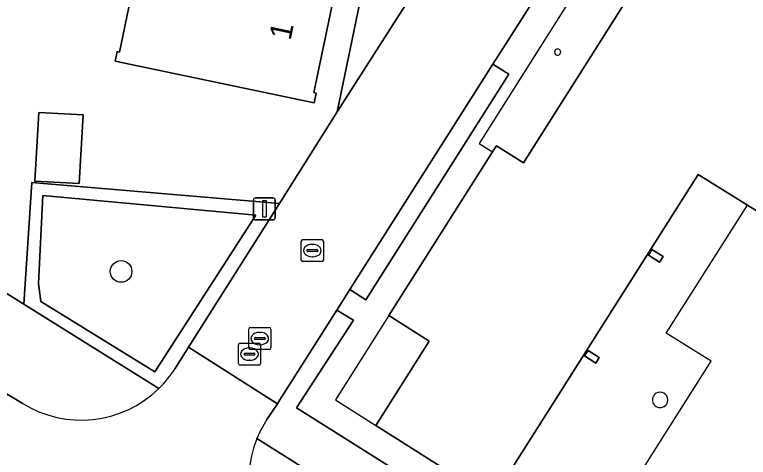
# Model space of a CAD drawing. Extents: x 160102 to 160934, y 382045 to 382923.
# Drawn here: x 160600.16 to 160633.3, y 382504.65 to 382524.66 of the extents above; entities that cross this region are included whole.
import ezdxf

# ---------------------------------------------------------------- set-up
doc = ezdxf.new("R2010")
doc.units = 0
for name, color, linetype in [('IMGEO_Boom', 7, 'Continuous'), ('IMGEO_Erf', 7, 'Continuous'), ('IMGEO_Groenvoorziening', 7, 'Continuous'), ('IMGEO_Haag', 7, 'Continuous'), ('IMGEO_Kolk', 7, 'Continuous'), ('IMGEO_Lichtmast', 7, 'Continuous'), ('IMGEO_Pand', 7, 'Continuous'), ('IMGEO_Pand_nummerreeks', 7, 'Continuous'), ('IMGEO_Pand_overbouw', 7, 'Continuous'), ('IMGEO_Rijbaan_lokaal_open', 7, 'Continuous'), ('IMGEO_Rioolput', 7, 'Continuous'), ('IMGEO_Voetpad_open', 7, 'Continuous')]:
    doc.layers.add(name, color=color, linetype=linetype)

msp = doc.modelspace()

# ---------------------------------------------------------------- linework, layer by layer
at = {"layer": 'IMGEO_Boom'}
msp.add_circle((160604.963, 382513.056), 0.489, dxfattribs=at)
at = {"layer": 'IMGEO_Erf'}
for points in [[(160597.213, 382513.675), (160600.569, 382511.579), (160600.937, 382517.084), (160612.115, 382516.132), (160614.729, 382520.276), (160621.393, 382552.466), (160644.153, 382585.048), (160643.411, 382585.751)], [(160661.29, 382563.07), (160652.176, 382568.858), (160644.821, 382557.292), (160644.14, 382557.763), (160641.367, 382553.385), (160642.088, 382552.972), (160635.737, 382542.872), (160634.993, 382543.323), (160634.373, 382542.344), (160635.122, 382541.901), (160631.677, 382536.462), (160630.951, 382536.942), (160630.329, 382535.96), (160631.075, 382535.503), (160624.503, 382525.174), (160623.784, 382525.627), (160621.753, 382522.421), (160622.486, 382521.975), (160616.017, 382511.774), (160615.304, 382512.24), (160614.712, 382511.306), (160615.463, 382510.851), (160612.895, 382506.892), (160621.64, 382501.381)], [(160623.035, 382501.942), (160616.467, 382506.097), (160618.877, 382509.909), (160617.058, 382511.061), (160621.744, 382518.47), (160621.915, 382518.741), (160623.138, 382517.968), (160628.549, 382526.524), (160627.327, 382527.296), (160632.166, 382534.971), (160633.99, 382533.819), (160638.509, 382540.958), (160636.686, 382542.112), (160641.372, 382549.513), (160641.543, 382549.784), (160642.75, 382549.033), (160649.656, 382559.892), (160648.437, 382560.667), (160652.564, 382567.156), (160660.609, 382562.063)], [(160656.657, 382547.701), (160653.009, 382541.939), (160650.588, 382543.471), (160648.386, 382544.865), (160634.7, 382523.243), (160636.962, 382521.806), (160639.295, 382520.324), (160635.687, 382514.541), (160633.257, 382516.056), (160631.03, 382517.445), (160622.018, 382503.2)], [(160614.735, 382526.271), (160613.666, 382521.142), (160613.774, 382521.12), (160613.683, 382520.684), (160604.691, 382522.561), (160604.781, 382522.997), (160604.889, 382522.975), (160605.736, 382527.058)]]:
    msp.add_lwpolyline(points, dxfattribs=at)
for points in [[(160603.248, 382520.134), (160603.071, 382517.029), (160601.074, 382517.143), (160601.251, 382520.248)], [(160629.447, 382513.727), (160629.287, 382513.473), (160628.78, 382513.794), (160628.94, 382514.048)], [(160626.564, 382509.169), (160626.403, 382508.916), (160625.896, 382509.237), (160626.057, 382509.49)]]:
    msp.add_lwpolyline(points, close=True, dxfattribs=at)
for centre, radius, start, end in [((160624.682, 382522.973), 0.14, 119.8953, 359.7956), ((160624.682, 382522.974), 0.14, 359.6914, 119.9995), ((160629.312, 382507.253), 0.35, 0.0178, 120), ((160629.312, 382507.253), 0.35, 120.0178, 0)]:
    msp.add_arc(centre, radius, start, end, dxfattribs=at)
at = {"layer": 'IMGEO_Groenvoorziening'}
for points in [[(160621.753, 382522.421), (160615.304, 382512.24), (160616.017, 382511.774), (160622.486, 382521.975)], [(160611.05, 382515.602), (160606.488, 382508.518), (160601.346, 382511.706), (160601.235, 382512.516), (160601.432, 382516.495)], [(160611.05, 382515.602), (160601.432, 382516.495), (160601.235, 382512.516), (160601.346, 382511.706), (160606.488, 382508.518)]]:
    msp.add_lwpolyline(points, close=True, dxfattribs=at)
for points in [[(160600.937, 382517.084), (160600.569, 382511.579), (160606.673, 382507.766)], [(160607.407, 382508.669), (160608.012, 382509.628), (160612.115, 382516.132), (160600.937, 382517.084)], [(160612.895, 382506.892), (160615.463, 382510.851), (160614.712, 382511.306), (160612.141, 382507.247), (160612.026, 382507.073), (160611.554, 382506.362)], [(160611.1, 382505.501), (160620.525, 382499.569), (160621.64, 382501.381), (160612.895, 382506.892)]]:
    msp.add_lwpolyline(points, dxfattribs=at)
for centre, radius, start, end in [((160603.16, 382511.372), 5.034, 314.2573, 327.5311), ((160615.692, 382503.63), 4.959, 146.5654, 157.8298)]:
    msp.add_arc(centre, radius, start, end, dxfattribs=at)
at = {"layer": 'IMGEO_Haag'}
for points in [[(160612.115, 382516.132), (160600.937, 382517.084), (160600.569, 382511.579), (160606.673, 382507.766)], [(160607.407, 382508.669), (160608.012, 382509.628), (160612.115, 382516.132)]]:
    msp.add_lwpolyline(points, dxfattribs=at)
msp.add_lwpolyline([(160606.488, 382508.518), (160601.346, 382511.706), (160601.235, 382512.516), (160601.432, 382516.495), (160611.05, 382515.602)], close=True, dxfattribs=at)
msp.add_arc((160603.16, 382511.372), 5.034, 314.2573, 327.5311, dxfattribs=at)
at = {"layer": 'IMGEO_Kolk'}
for p, q in [((160613.103, 382513.574), (160613.103, 382514.426)), ((160613.178, 382514.5), (160614.03, 382514.5)), ((160613.591, 382514.28), (160613.616, 382514.28)), ((160614.104, 382514.426), (160614.104, 382513.574)), ((160613.362, 382513.994), (160613.362, 382514.006)), ((160613.8, 382513.957), (160613.402, 382513.957)), ((160613.405, 382514.043), (160613.803, 382514.043)), ((160613.846, 382514.006), (160613.846, 382513.994)), ((160613.614, 382513.72), (160613.589, 382513.72)), ((160614.03, 382513.5), (160613.178, 382513.5))]:
    msp.add_line(p, q, dxfattribs=at)
for points in [[(160613.103, 382513.574), (160613.103, 382514.426)], [(160613.178, 382514.5), (160614.03, 382514.5)], [(160614.104, 382514.426), (160614.104, 382513.574)], [(160614.03, 382513.5), (160613.178, 382513.5)]]:
    msp.add_lwpolyline(points, dxfattribs=at)
for centre, radius, start, end in [((160613.18, 382514.424), 0.0765, 91.552, 178.448), ((160613.18, 382514.424), 0.0765, 91.552, 178.448), ((160614.028, 382514.424), 0.0765, 1.552, 88.448), ((160614.028, 382514.424), 0.0765, 1.552, 88.448), ((160613.402, 382514.003), 0.0403, 85.8775, 175.7526), ((160613.399, 382513.993), 0.0366, 178.938, 274.7102), ((160613.803, 382514), 0.043, 264.8664, 352.4533), ((160613.807, 382514.005), 0.0386, 1.7309, 96.639), ((160613.18, 382513.576), 0.0765, 181.552, 268.448), ((160613.18, 382513.576), 0.0765, 181.552, 268.448), ((160614.028, 382513.576), 0.0765, 271.552, 358.448), ((160614.028, 382513.576), 0.0765, 271.552, 358.448)]:
    msp.add_arc(centre, radius, start, end, dxfattribs=at)
for centre, major_axis, ratio, start_param, end_param in [((160613.59, 382514), (-0.387, 0.002), 0.722429, 4.712389, 7.853982), ((160613.615, 382514), (-0.39, 0.002), 0.717154, 1.570796, 4.712389)]:
    msp.add_ellipse(centre, major_axis=major_axis, ratio=ratio, start_param=start_param, end_param=end_param, dxfattribs=at)
at = {"layer": 'IMGEO_Lichtmast'}
for p, q in [((160610.94, 382515.484), (160610.94, 382516.284)), ((160610.94, 382516.284), (160610.94, 382515.484)), ((160611.04, 382516.384), (160611.83, 382516.384)), ((160611.83, 382516.384), (160611.04, 382516.384)), ((160611.93, 382516.284), (160611.93, 382515.484)), ((160611.93, 382515.484), (160611.93, 382516.284)), ((160611.83, 382515.384), (160611.04, 382515.384)), ((160611.04, 382515.384), (160611.83, 382515.384))]:
    msp.add_line(p, q, dxfattribs=at)
msp.add_lwpolyline([(160611.36, 382516.259), (160611.51, 382516.259), (160611.51, 382515.509), (160611.36, 382515.509), (160611.36, 382516.259)], dxfattribs=at)
for centre, start, end in [((160611.04, 382516.284), 90, 180), ((160611.04, 382516.284), 90, 180), ((160611.83, 382516.284), 0, 90), ((160611.83, 382516.284), 360, 90), ((160611.04, 382515.484), 180, 270), ((160611.04, 382515.484), 180, 270), ((160611.83, 382515.484), 270, 0), ((160611.83, 382515.484), 270, 0)]:
    msp.add_arc(centre, 0.1, start, end, dxfattribs=at)
at = {"layer": 'IMGEO_Pand'}
for points in [[(160660.609, 382562.063), (160652.564, 382567.156), (160648.437, 382560.667), (160649.656, 382559.892), (160642.75, 382549.033), (160641.543, 382549.784), (160641.372, 382549.513), (160636.686, 382542.112), (160638.509, 382540.958), (160633.99, 382533.819), (160632.166, 382534.971), (160627.327, 382527.296), (160628.549, 382526.524), (160623.138, 382517.968), (160621.915, 382518.741), (160621.744, 382518.47), (160617.058, 382511.061), (160618.877, 382509.909), (160616.467, 382506.097), (160623.035, 382501.942)], [(160622.018, 382503.2), (160631.03, 382517.445), (160633.257, 382516.056), (160635.687, 382514.541), (160639.295, 382520.324), (160636.962, 382521.806), (160634.7, 382523.243), (160648.386, 382544.865), (160650.588, 382543.471), (160653.009, 382541.939), (160656.657, 382547.701)]]:
    msp.add_lwpolyline(points, dxfattribs=at)
for points in [[(160614.735, 382526.271), (160605.952, 382528.102), (160605.736, 382527.058), (160604.889, 382522.975), (160604.781, 382522.997), (160604.691, 382522.561), (160613.683, 382520.684), (160613.774, 382521.12), (160613.666, 382521.142)], [(160603.248, 382520.134), (160601.251, 382520.248), (160601.074, 382517.143), (160603.071, 382517.029)], [(160628.94, 382514.048), (160628.78, 382513.794), (160629.287, 382513.473), (160629.447, 382513.727)], [(160626.057, 382509.49), (160625.896, 382509.237), (160626.403, 382508.916), (160626.564, 382509.169)]]:
    msp.add_lwpolyline(points, close=True, dxfattribs=at)
for centre, radius, start, end in [((160624.682, 382522.973), 0.14, 119.8953, 359.7956), ((160624.682, 382522.974), 0.14, 359.6914, 119.9995), ((160629.312, 382507.253), 0.35, 0.0178, 120), ((160629.312, 382507.253), 0.35, 120.0178, 0)]:
    msp.add_arc(centre, radius, start, end, dxfattribs=at)
at = {"layer": 'IMGEO_Pand_overbouw'}
for points in [[(160632.166, 382534.971), (160631.556, 382535.355), (160626.758, 382527.747), (160621.146, 382518.848), (160621.744, 382518.47), (160621.915, 382518.741), (160623.138, 382517.968), (160628.549, 382526.524), (160627.327, 382527.296)], [(160631.613, 382508.998), (160629.582, 382510.267), (160633.257, 382516.056), (160631.03, 382517.445), (160622.018, 382503.2), (160622.561, 382502.857), (160622.454, 382502.688), (160623.206, 382502.212), (160623.035, 382501.942), (160625.973, 382500.083)], [(160617.058, 382511.061), (160614.647, 382507.248), (160616.467, 382506.097), (160618.877, 382509.909)]]:
    msp.add_lwpolyline(points, close=True, dxfattribs=at)
at = {"layer": 'IMGEO_Rijbaan_lokaal_open'}
for points in [[(160626.831, 382539.382), (160621.969, 382531.692), (160618.512, 382526.228), (160614.729, 382520.276), (160612.115, 382516.132), (160608.012, 382509.628), (160612.026, 382507.073), (160612.141, 382507.247), (160614.712, 382511.306), (160615.304, 382512.24), (160621.753, 382522.421), (160623.784, 382525.627), (160630.329, 382535.96), (160630.951, 382536.942), (160634.373, 382542.344), (160634.993, 382543.323), (160641.367, 382553.385), (160644.14, 382557.763), (160650.804, 382568.283)], [(160612.026, 382507.073), (160608.012, 382509.628), (160607.407, 382508.669)], [(160600.492, 382507.103), (160599.823, 382507.515), (160596.654, 382502.346), (160600.442, 382500), (160610.528, 382493.753), (160613.732, 382498.897), (160613.012, 382499.329)], [(160611.554, 382506.362), (160612.026, 382507.073)]]:
    msp.add_lwpolyline(points, dxfattribs=at)
for centre, radius, start, end in [((160603.16, 382511.372), 5.034, 314.2573, 327.5311), ((160603.161, 382511.368), 5.031, 237.9686, 314.2761), ((160615.692, 382503.63), 4.959, 146.5654, 157.8298), ((160615.796, 382503.574), 5.076, 157.6841, 236.7404)]:
    msp.add_arc(centre, radius, start, end, dxfattribs=at)
at = {"layer": 'IMGEO_Rioolput'}
for p, q in [((160610.727, 382509.598), (160610.727, 382510.45)), ((160610.802, 382510.524), (160611.654, 382510.524)), ((160611.215, 382510.304), (160611.24, 382510.304)), ((160611.728, 382510.45), (160611.728, 382509.598)), ((160610.986, 382510.018), (160610.986, 382510.03)), ((160611.424, 382509.981), (160611.026, 382509.981)), ((160611.029, 382510.067), (160611.427, 382510.067)), ((160611.47, 382510.03), (160611.47, 382510.018)), ((160610.264, 382508.894), (160610.264, 382509.746)), ((160610.339, 382509.82), (160611.191, 382509.82)), ((160610.752, 382509.6), (160610.777, 382509.6)), ((160611.238, 382509.744), (160611.213, 382509.744)), ((160611.265, 382509.746), (160611.265, 382508.894)), ((160610.523, 382509.314), (160610.523, 382509.326)), ((160610.961, 382509.277), (160610.563, 382509.277)), ((160610.566, 382509.363), (160610.964, 382509.363)), ((160611.654, 382509.524), (160610.802, 382509.524)), ((160611.007, 382509.326), (160611.007, 382509.314)), ((160610.775, 382509.04), (160610.75, 382509.04)), ((160611.191, 382508.82), (160610.339, 382508.82))]:
    msp.add_line(p, q, dxfattribs=at)
for points in [[(160610.727, 382509.598), (160610.727, 382510.45)], [(160610.802, 382510.524), (160611.654, 382510.524)], [(160611.728, 382510.45), (160611.728, 382509.598)], [(160610.264, 382508.894), (160610.264, 382509.746)], [(160610.339, 382509.82), (160611.191, 382509.82)], [(160611.265, 382509.746), (160611.265, 382508.894)], [(160611.654, 382509.524), (160610.802, 382509.524)], [(160611.191, 382508.82), (160610.339, 382508.82)]]:
    msp.add_lwpolyline(points, dxfattribs=at)
for centre, radius, start, end in [((160610.804, 382510.448), 0.0765, 91.552, 178.448), ((160610.804, 382510.448), 0.0765, 91.552, 178.448), ((160611.652, 382510.448), 0.0765, 1.552, 88.448), ((160611.652, 382510.448), 0.0765, 1.552, 88.448), ((160611.026, 382510.027), 0.0403, 85.8775, 175.7526), ((160611.023, 382510.017), 0.0366, 178.938, 274.7102), ((160611.427, 382510.024), 0.043, 264.8664, 352.4533), ((160611.431, 382510.029), 0.0386, 1.7309, 96.639), ((160610.341, 382509.744), 0.0765, 91.552, 178.448), ((160610.341, 382509.744), 0.0765, 91.552, 178.448), ((160610.804, 382509.6), 0.0765, 181.552, 268.448), ((160610.804, 382509.6), 0.0765, 181.552, 268.448), ((160611.189, 382509.744), 0.0765, 1.552, 88.448), ((160611.189, 382509.744), 0.0765, 1.552, 88.448), ((160611.652, 382509.6), 0.0765, 271.552, 358.448), ((160611.652, 382509.6), 0.0765, 271.552, 358.448), ((160610.563, 382509.323), 0.0403, 85.8775, 175.7526), ((160610.56, 382509.313), 0.0366, 178.938, 274.7102), ((160610.964, 382509.32), 0.043, 264.8664, 352.4533), ((160610.968, 382509.325), 0.0386, 1.7309, 96.639), ((160610.341, 382508.896), 0.0765, 181.552, 268.448), ((160610.341, 382508.896), 0.0765, 181.552, 268.448), ((160611.189, 382508.896), 0.0765, 271.552, 358.448), ((160611.189, 382508.896), 0.0765, 271.552, 358.448)]:
    msp.add_arc(centre, radius, start, end, dxfattribs=at)
for centre, major_axis, ratio, start_param, end_param in [((160611.214, 382510.024), (-0.387, 0.002), 0.722429, 4.712389, 7.853982), ((160611.239, 382510.024), (-0.39, 0.002), 0.717154, 1.570796, 4.712389), ((160610.751, 382509.32), (-0.387, 0.002), 0.722429, 4.712389, 7.853982), ((160610.776, 382509.32), (-0.39, 0.002), 0.717154, 1.570796, 4.712389)]:
    msp.add_ellipse(centre, major_axis=major_axis, ratio=ratio, start_param=start_param, end_param=end_param, dxfattribs=at)
at = {"layer": 'IMGEO_Voetpad_open'}
for points in [[(160645.382, 382583.845), (160644.153, 382585.048), (160621.393, 382552.466), (160614.729, 382520.276), (160618.512, 382526.228)], [(160600.569, 382511.579), (160597.213, 382513.675), (160594.93, 382515.078), (160580.171, 382515.999), (160580.178, 382516.126), (160579.471, 382516.183), (160579.22, 382512.098), (160580.281, 382512.958)], [(160606.673, 382507.766), (160600.569, 382511.579)], [(160599.648, 382507.623), (160599.823, 382507.515), (160600.492, 382507.103)], [(160620.525, 382499.569), (160611.1, 382505.501)]]:
    msp.add_lwpolyline(points, dxfattribs=at)
for centre, radius, start, end in [((160603.161, 382511.368), 5.031, 237.9686, 314.2761), ((160615.796, 382503.574), 5.076, 157.6841, 236.7404)]:
    msp.add_arc(centre, radius, start, end, dxfattribs=at)

# ---------------------------------------------------------------- texts
at = {"layer": 'IMGEO_Pand_nummerreeks'}
msp.add_text('1', height=1, rotation=78.2259, dxfattribs=at).set_placement((160612.618, 382523.47))

doc.saveas('drawing.dxf')
